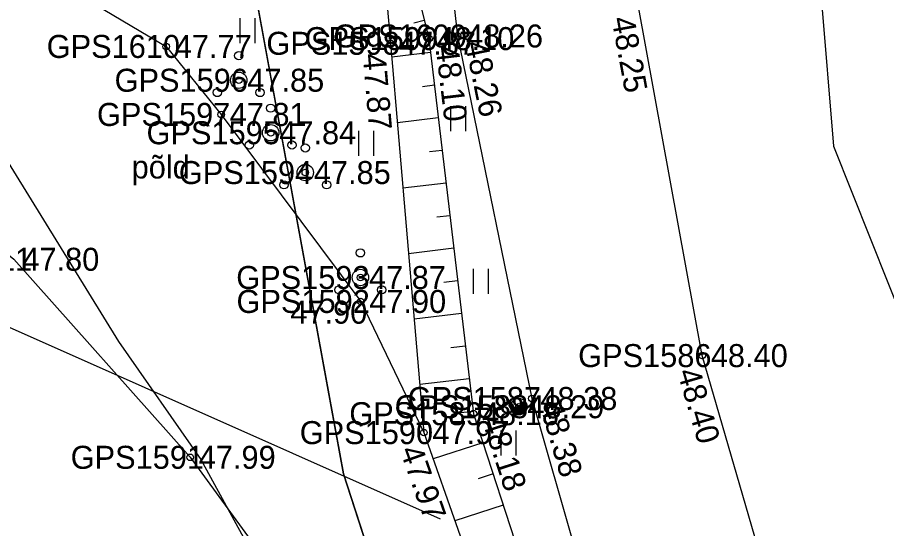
# Model space of a CAD drawing. Extents: x 551623 to 559850, y 6561220 to 6567135.
# Drawn here: x 555050.49 to 555076.95, y 6565581.59 to 6565597.16 of the extents above; entities that cross this region are included whole.
import ezdxf

# ---------------------------------------------------------------- set-up
doc = ezdxf.new("R2010")
doc.units = 0
for name, color, linetype in [('DTRASS', 7, 'Continuous'), ('HALJASTUS', 7, 'Continuous'), ('KORGUS-EH2000', 7, 'Continuous'), ('KPKAABEL', 7, 'Continuous'), ('MOOTKORG-EH2000', 7, 'Continuous'), ('MOOTMPUNKT', 7, 'Continuous'), ('MOOTNR', 7, 'Continuous'), ('MOOTPIIR', 7, 'Continuous'), ('PIIR', 7, 'Continuous'), ('POST', 7, 'Continuous'), ('PUU', 7, 'Continuous'), ('RELJEEF', 7, 'Continuous'), ('TEE', 7, 'Continuous')]:
    doc.layers.add(name, color=color, linetype=linetype)

msp = doc.modelspace()

# ---------------------------------------------------------------- linework, layer by layer
at = {"layer": 'DTRASS'}
msp.add_line((555063.371, 6565581.881), (555027.329, 6565597.89), dxfattribs=at)
at = {"layer": 'HALJASTUS'}
for p, q in [((555057.264, 6565597.135), (555057.264, 6565596.374)), ((555057.719, 6565597.135), (555057.719, 6565596.374)), ((555063.674, 6565594.45), (555063.674, 6565593.689)), ((555064.129, 6565594.45), (555064.129, 6565593.689)), ((555060.874, 6565593.707), (555060.874, 6565592.946)), ((555061.329, 6565593.707), (555061.329, 6565592.946)), ((555064.365, 6565589.498), (555064.365, 6565588.737)), ((555064.82, 6565589.498), (555064.82, 6565588.737)), ((555065.207, 6565584.581), (555065.207, 6565583.82)), ((555065.662, 6565584.581), (555065.662, 6565583.82))]:
    msp.add_line(p, q, dxfattribs=at)
msp.add_lwpolyline([(555033.078, 6565606.955), (555042.182, 6565603.884), (555055.024, 6565596.272), (555056.694, 6565594.201), (555060.942, 6565588.507), (555062.867, 6565584.513)], dxfattribs=at)
at = {"layer": 'KORGUS-EH2000'}
for centre in [(555063.017, 6565596.511), (555063.892, 6565596.591), (555055.024, 6565596.272), (555061.852, 6565596.368), (555060.942, 6565588.507), (555071.343, 6565586.858), (555066.154, 6565585.551), (555064.375, 6565585.09), (555062.867, 6565584.513), (555055.753, 6565583.761)]:
    msp.add_circle(centre, 0.1, dxfattribs=at)
at = {"layer": 'KPKAABEL'}
msp.add_lwpolyline([(555016.436, 6565669.854), (555020.596, 6565667.742), (555021.693, 6565667.12), (555022.688, 6565666.158), (555023.697, 6565665.37), (555024.08, 6565664.769), (555021.622, 6565652.627), (555021.526, 6565649.765), (555022.786, 6565647.231), (555026.485, 6565641.465), (555030.606, 6565629.728), (555035.378, 6565618.813), (555040.844, 6565608.057), (555047.089, 6565597.805), (555053.567, 6565587.292), (555056.073, 6565583.696), (555062.108, 6565572.667), (555068.248, 6565560.982)], dxfattribs=at)
at = {"layer": 'MOOTMPUNKT'}
for centre in [(555063.017, 6565596.511), (555063.892, 6565596.591), (555055.024, 6565596.272), (555061.852, 6565596.368), (555057.23, 6565595.243), (555056.694, 6565594.201), (555058.203, 6565593.644), (555059.256, 6565592.432), (555060.934, 6565589.236), (555060.942, 6565588.507), (555071.343, 6565586.858), (555066.154, 6565585.551), (555064.375, 6565585.09), (555065.758, 6565585.302), (555062.867, 6565584.513), (555055.753, 6565583.761)]:
    msp.add_circle(centre, 0.1, dxfattribs=at)
at = {"layer": 'MOOTPIIR'}
for points in [[(555026.508, 6565625.245), (555032.663, 6565611.321), (555033.078, 6565606.955), (555039.99, 6565598.181), (555050.382, 6565589.791), (555055.753, 6565583.761), (555063.202, 6565573.546), (555069.448, 6565559.262)], [(555079.648, 6565563.241), (555074.002, 6565577.71), (555071.343, 6565586.858), (555069.389, 6565597.535), (555068.634, 6565604.431), (555063.038, 6565604.031), (555061.195, 6565603.857), (555048.79, 6565618.739)]]:
    msp.add_lwpolyline(points, dxfattribs=at)
at = {"layer": 'PIIR'}
for points in [[(555524.79, 6565820.16), (555464.46, 6565652.92), (555447.97, 6565611.96), (555353.12, 6565523.87), (555343.14, 6565512.46), (555302.6, 6565539.71), (555242.37, 6565583.94), (555179.42, 6565586.32), (555138.98, 6565580.6), (555121.18, 6565602.26), (555116.17, 6565610.5), (555109.96, 6565624.83), (555093.56, 6565628.47), (555079.04, 6565618.4), (555074.13, 6565607.82), (555075.34, 6565593.24), (555091.74, 6565551.94), (555171.91, 6565394.64), (555191.35, 6565341.19)], [(554759.9, 6565289.12), (554708.97, 6565534.83), (554708.61, 6565545.48), (554711.27, 6565557.85), (554755.81, 6565778.04), (554759.53, 6565776.27), (554842.52, 6565736.67), (555030.24, 6565648.23), (555043.11, 6565640.11), (555053.62, 6565632.14), (555056.61, 6565622.91), (555057.22, 6565600.73), (555060.42, 6565583.26), (555065.78, 6565566.7), (555076.76, 6565542.38), (555113.82, 6565475.68), (554946.63, 6565420.78), (554981.01, 6565316.76), (555160.07, 6565375.54), (555166.64, 6565360.5), (555172.72, 6565345.23)], [(555172.72, 6565345.23), (555166.64, 6565360.5), (555160.07, 6565375.54), (555144.16, 6565410.6), (555124.27, 6565454.45), (555113.82, 6565475.68), (555076.76, 6565542.38), (555065.78, 6565566.7), (555060.42, 6565583.26), (555057.22, 6565600.73), (555056.61, 6565622.91), (555063.43, 6565647.29), (555114.24, 6565634), (555129.77, 6565611.2), (555130.73, 6565621.32), (555138.66, 6565615.26), (555160.12, 6565598.86), (555193.24, 6565604.68)]]:
    msp.add_lwpolyline(points, dxfattribs=at)
at = {"layer": 'POST'}
msp.add_line((555065.581, 6565585.125), (555065.934, 6565585.478), dxfattribs=at)
msp.add_circle((555065.758, 6565585.302), 0.25, dxfattribs=at)
for radius, start, end in [(0.225, 224.8541, 45.0356), (0.2, 224.8427, 45.047), (0.175, 224.8281, 45.0616), (0.15, 224.8087, 45.081), (0.125, 224.7814, 45.1083), (0.1, 224.7406, 45.1491), (0.075, 224.6725, 45.2172), (0.05, 224.5363, 45.3534), (0.025, 224.1278, 45.7619)]:
    msp.add_arc((555065.758, 6565585.302), radius, start, end, dxfattribs=at)
at = {"layer": 'PUU'}
for centre, radius in [((555057.23, 6565595.993), 0.125), ((555057.23, 6565595.243), 0.25), ((555056.579, 6565594.868), 0.125), ((555057.88, 6565594.868), 0.125), ((555058.203, 6565594.394), 0.125), ((555058.203, 6565593.644), 0.25), ((555057.552, 6565593.269), 0.125), ((555058.853, 6565593.269), 0.125), ((555059.256, 6565593.182), 0.125), ((555059.256, 6565592.432), 0.25), ((555058.606, 6565592.057), 0.125), ((555059.906, 6565592.057), 0.125), ((555060.934, 6565589.986), 0.125), ((555060.934, 6565589.236), 0.25), ((555060.284, 6565588.861), 0.125), ((555061.584, 6565588.861), 0.125)]:
    msp.add_circle(centre, radius, dxfattribs=at)
at = {"layer": 'RELJEEF'}
for p, q in [((555062.88, 6565597.064), (555062.56, 6565596.984)), ((555063.068, 6565596.083), (555061.888, 6565595.943)), ((555063.186, 6565595.09), (555062.823, 6565595.047)), ((555063.304, 6565594.097), (555062.059, 6565593.949)), ((555063.423, 6565593.104), (555063.039, 6565593.059)), ((555063.541, 6565592.111), (555062.229, 6565591.955)), ((555063.659, 6565591.118), (555063.256, 6565591.07)), ((555063.777, 6565590.125), (555062.4, 6565589.962)), ((555063.895, 6565589.132), (555063.472, 6565589.082)), ((555064.013, 6565588.139), (555062.571, 6565587.968)), ((555064.131, 6565587.146), (555063.689, 6565587.094)), ((555064.249, 6565586.153), (555062.742, 6565585.974)), ((555064.367, 6565585.16), (555063.905, 6565585.105)), ((555064.663, 6565584.206), (555063.147, 6565583.714)), ((555064.972, 6565583.255), (555064.524, 6565583.11)), ((555065.281, 6565582.304), (555063.811, 6565581.826))]:
    msp.add_line(p, q, dxfattribs=at)
for points in [[(555061.195, 6565603.857), (555063.017, 6565596.511), (555064.375, 6565585.09), (555067.439, 6565575.666), (555073.66, 6565560.25), (555078.569, 6565547.982), (555085.069, 6565536.269), (555098.285, 6565513.031), (555109.976, 6565491.648), (555121.815, 6565470.323), (555129.412, 6565453.415), (555139.708, 6565430.653), (555142.38, 6565424.284), (555142.548, 6565422.18)], [(555061.195, 6565603.857), (555061.852, 6565596.368), (555062.867, 6565584.513), (555066.182, 6565575.081), (555072.102, 6565560.271), (555077.804, 6565547.739), (555084.384, 6565535.83), (555097.578, 6565512.389), (555109.285, 6565491.27), (555120.826, 6565469.686), (555128.698, 6565452.867), (555138.479, 6565430.174), (555141.354, 6565423.963), (555142.548, 6565422.18)]]:
    msp.add_lwpolyline(points, dxfattribs=at)
at = {"layer": 'TEE'}
for points in [[(555183.958, 6565348.1), (555179.78, 6565359.387), (555170.643, 6565380.205), (555162.823, 6565397.349), (555156.491, 6565411.721), (555150.933, 6565424.006), (555146.697, 6565433.416), (555136.695, 6565455.531), (555128.269, 6565473.276), (555117.193, 6565494.735), (555104.647, 6565516.948), (555091.543, 6565539.738), (555085.215, 6565551.468), (555079.648, 6565563.241), (555074.002, 6565577.71), (555071.343, 6565586.858), (555069.389, 6565597.535), (555068.634, 6565604.431)], [(555063.038, 6565604.031), (555063.892, 6565596.591), (555066.154, 6565585.551), (555068.837, 6565576.18), (555074.683, 6565560.943), (555080.389, 6565548.865), (555086.718, 6565537.194), (555099.86, 6565513.945), (555112.002, 6565492.197), (555123.272, 6565470.871), (555131.266, 6565453.894), (555141.635, 6565431.431), (555145.957, 6565421.634), (555151.76, 6565408.809), (555158.151, 6565395.066), (555165.93, 6565378.047), (555174.733, 6565357.312)]]:
    msp.add_lwpolyline(points, dxfattribs=at)

# ---------------------------------------------------------------- texts
at = {"layer": 'HALJASTUS'}
msp.add_text('põld', height=0.7, rotation=359.9544, dxfattribs=at).set_placement((555053.97, 6565592.252))
at = {"layer": 'KORGUS-EH2000'}
for s, rotation, p in [(' 48.25', 280.3725, (555068.528, 6565597.378)), (' 48.10', 276.7809, (555063.191, 6565596.532)), (' 48.26', 281.578, (555064.063, 6565596.626)), (' 47.87', 274.8926, (555060.98, 6565596.293)), (' 48.40', 286.2097, (555070.503, 6565586.614)), (' 48.38', 285.9778, (555066.322, 6565585.6)), (' 48.18', 288.0079, (555064.542, 6565585.145)), (' 47.97', 289.3678, (555062.041, 6565584.222))]:
    msp.add_text(s, height=0.7, rotation=rotation, dxfattribs=at).set_placement(p)
for s, p in [(' 47.77', (555055.024, 6565595.922)), (' 47.80', (555050.382, 6565589.441)), (' 47.90', (555058.541, 6565587.83)), (' 47.99', (555055.753, 6565583.411))]:
    msp.add_text(s, height=0.7, dxfattribs=at).set_placement(p)
at = {"layer": 'MOOTKORG-EH2000'}
for s, p in [(' 48.10', (555063.017, 6565596.161)), (' 48.26', (555063.892, 6565596.241)), (' 47.77', (555055.024, 6565595.922)), (' 47.87', (555061.852, 6565596.018)), (' 47.85', (555057.23, 6565594.893)), (' 47.81', (555056.694, 6565593.851)), (' 47.84', (555058.203, 6565593.294)), (' 47.85', (555059.256, 6565592.082)), (' 47.80', (555050.382, 6565589.441)), (' 47.87', (555060.934, 6565588.886)), (' 47.90', (555060.942, 6565588.157)), (' 48.40', (555071.343, 6565586.508)), (' 48.38', (555066.154, 6565585.201)), (' 48.18', (555064.375, 6565584.74)), (' 48.29', (555065.758, 6565584.951)), (' 47.97', (555062.867, 6565584.163)), (' 47.99', (555055.753, 6565583.411))]:
    msp.add_text(s, height=0.7, dxfattribs=at).set_placement(p)
at = {"layer": 'MOOTNR'}
for s, p in [('GPS1599 ', (555059.238, 6565596.161)), ('GPS1600 ', (555060.112, 6565596.241)), ('GPS1610 ', (555051.384, 6565595.922)), ('GPS1598 ', (555058.072, 6565596.018)), ('GPS1596 ', (555053.45, 6565594.893)), ('GPS1597 ', (555052.915, 6565593.851)), ('GPS1595 ', (555054.423, 6565593.294)), ('GPS1594 ', (555055.406, 6565592.082)), ('GPS1611 ', (555046.882, 6565589.441)), ('GPS1593 ', (555057.154, 6565588.886)), ('GPS1592 ', (555057.162, 6565588.157)), ('GPS1586 ', (555067.563, 6565586.508)), ('GPS1587 ', (555062.374, 6565585.201)), ('GPS1589 ', (555060.596, 6565584.74)), ('GPS1588 ', (555061.978, 6565584.951)), ('GPS1590 ', (555059.087, 6565584.163)), ('GPS1591 ', (555052.113, 6565583.411))]:
    msp.add_text(s, height=0.7, dxfattribs=at).set_placement(p)

doc.saveas('drawing.dxf')
